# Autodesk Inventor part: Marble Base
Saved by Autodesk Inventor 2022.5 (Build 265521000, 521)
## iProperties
Created: 2025-02
Part Number: Marble Base
Material: Generic
Document SubType Name: Modeling
Designer: AdminForWorker
Density: 1 g/cm^3
Appearance: Default
Title: Marble Base
Author: AdminForWorker
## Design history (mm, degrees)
feature "Marble Base"
body "Solid1"
